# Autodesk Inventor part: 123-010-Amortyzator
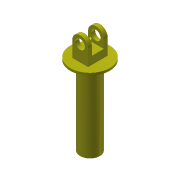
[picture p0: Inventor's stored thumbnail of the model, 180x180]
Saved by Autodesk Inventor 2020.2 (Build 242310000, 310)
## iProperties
Created: 2014-12
Part Number: 123-010-Amortyzator
Material: Aluminium 6061
Document SubType Name: Modeling
Designer: F.Stasiak
Density: 2.7 g/cm^3
Appearance: Żółta
Mass: 56.3494 g
Surface Area: 220.45 cm^2
Volume: 20.8701 cm^3
Catalog Web Link: www.expertbooks.pl
Manager: www.cadconsulting.pl
Company: Fabian Stasiak CAD Consulting
Author: F.Stasiak
Subject: Zbiór ćwiczeń. Autodesk Inventor 2020. Kurs Professional
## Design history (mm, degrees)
sketch "Szkic1"
  geometry: C1 r 25 at (0, 0); 1 further point
  constraints: 1 centre point, 1 coincident
  dimensions: "d0" = 50 diameter of C1
extrude "Wyciągnięcie proste1" new body sketch "Szkic1" distance "d1" = 3; taper "d2" = 0 deg
sketch "Szkic2"
  geometry: L1 (-10, 12.5)-(10, 12.5); L2 (10, 12.5)-(10, -12.5); L3 (10, -12.5)-(-10, -12.5); L4 (-10, -12.5)-(-10, 12.5); L5 (-10, 12.5)-(10, -12.5); L6 (10, 12.5)-(-10, -12.5); 1 further point
  constraints: 12 end point, 2 equal length, 2 midpoint, 1 horizontal, 1 parallel
  dimensions: "d3" = 20 distance of L2.end L3.end; "d4" = 25 distance of L1.end L2.end
extrude "Wyciągnięcie proste2" join sketch "Szkic2" distance "d5" = 30; taper "d6" = 0 deg
sketch "Szkic3"
  geometry: L1 (0, 25)-(0, 0) reference; L2 (0, 25)-(-30, 25) reference; L3 (-30, 0)-(-30, 25) reference; L4 (0, 0)-(-30, 0) reference; L5 (-30, 20)-(-10, 20); L6 (-10, 20)-(-10, 5); L7 (-10, 5)-(-30, 5); L8 (-30, 5)-(-30, 20); 2 further points
  constraints: 8 end point, 2 midpoint, 2 parallel, 1 horizontal, 1 perpendicular
  dimensions: "d7" = 20 distance of L6.end L7.end; "d8" = 15 distance of L5.end L6.end
extrude "Wyciągnięcie proste3" cut sketch "Szkic3" extent not by distance; stored distance "d9" = 30; taper "d10" = 0 deg
fillet "Zaokrąglenie1" dims "d11" = 10 (= 0.5 x d3)
sketch "Szkic4"
  geometry: L1 (0, 0)-(0, 20) reference; L2 (20, 0)-(0, 0) reference; L3 (20, 0)-(20, 20) reference; C1 r 6 at (10, 20); A1 r 10 centre (10, 20) between (20, 20) and (0, 20) reference; 1 further point
  constraints: 1 centre point, 1 coincident
  dimensions: "d12" = 12 diameter of C1
extrude "Wyciągnięcie proste4" cut sketch "Szkic4" extent not by distance; stored distance "d13" = 30; taper "d14" = 0 deg
sketch "Szkic5"
  geometry: C1 r 11.5 at (0, 0); C2 r 12.5 at (0, 0); 1 further point
  constraints: 2 centre point, 2 coincident
  dimensions: "d15" = 23 diameter of C1; "d16" = 25 diameter of C2
extrude "Wyciągnięcie proste5" join sketch "Szkic5" distance "d17" = 100; taper "d18" = 0 deg
node "Punkt konstrukcyjny1"
  node "Oś konstrukcyjna1"
node "Bryła1"
node "Pętla rzutowana1"
node "Pętla rzutowana2"
